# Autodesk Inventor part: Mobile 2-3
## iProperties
Author: Philippe
Shininess: 20.0
Angle Display Precision: 2
Document Length Units: 11269
Document Angle Units: 11283
Document Time Units: 11279
Document Mass Units: 11290
Document Length Units Precision: 3
Document Angle Units Precision: 2
Compacted: False
PropertySet Name: _Private Model Information
Created: 2002-01
Part Number: Mobile 2-3
Material: Par défaut
Document SubType Name: Modélisation
Designer: Philippe
Control State: 0
Master: False
Checked Out: False
PropertySet Name: Design Tracking Control
Density: 0.0
Volumn: 0.0
Area: 0.0
PropertySet Name: Model Information
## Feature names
1. Révolution1 [Revolution]
2. Extrusion1
3. Extrusion2
4. Réseau circulaire1 [Circular Pattern]
5. Extrusion3
6. Réseau circulaire2 [Circular Pattern]
